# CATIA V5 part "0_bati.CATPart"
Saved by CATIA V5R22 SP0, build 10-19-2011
Part number: 0_bati
Bounding box of the stored display mesh (mm): x -17 to 20, y -50 to 50, z -50 to 50
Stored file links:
  C:\Users\pelt\Documents\0_TOTAL_ENIB_2022\0_COURS\EDM\S2\0_S2_EDM_2024P\10_rattrapage S2 EDM\0_bati.CATPart
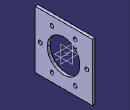
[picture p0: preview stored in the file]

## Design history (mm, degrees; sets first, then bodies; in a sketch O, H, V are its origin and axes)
Body1 (main body)
  Sketch1 on yz-plane, origin (0, 0, 0), H (0, 1, 0), V (0, 0, 1)
    line L1 (-50, 50) -> (50, 50)
    line L2 (50, 50) -> (50, -50)
    line L3 (50, -50) -> (-50, -50)
    line L4 (-50, -50) -> (-50, 50)
    reference intersected line E1 through (0, 0) direction (0, 1) from zx-plane
    reference intersected line E2 through (0, 0) direction (-1, 0) from xy-plane
    circle A1 centre (0, 0) radius 28.5
    point P5 (0, 0)
    reference intersected line E3 through (0, 0) direction (0, 1) from zx-plane
    reference intersected line E4 through (0, 0) direction (-1, 0) from xy-plane
    distance L2 L4 = 100
    distance L1 L3 = 100
    radius A1 = 28.5
    horizontal: L1 H, L3 H
    vertical: L2 V, L4 V
    symmetry: L2 L4 E1, L1 L3 E2
    coincidence: P5 E3, P5 E4
  Pad1: profile Sketch1, direction (1, 0, 0), length 5
  Point1: (0, 0, 0)
  Line1: type Normal, RefPoint Point1, RefSkin yz-plane, Start -17, End 20
  Sketch2 on end face of Pad1, origin (5, 18.6893, 39.5196), H (0, 1, 0), V (0, 0, 1)
    point P1 (21.8107, -39.5196)
    reference intersected line E1 through (0, -39.5196) direction (-1, 0) from xy-plane
    construction circle A1 centre (-18.6893, -39.5196) radius 40.5
    point P2 (-18.6893, -39.5196)
    reference intersected line E2 through (0, -39.5196) direction (-1, 0) from xy-plane
    reference intersected line E3 through (-18.6893, 0) direction (0, 1) from zx-plane
    radius A1 = 40.5
    coincidence: P1 E1, P2 E2, P2 E3, P1 A1
  Hole1: placed by Sketch2, at (5, 40.5, 0) direction (-1, 0, 0), diameter 6.5, through (limit type 6)
  CircPattern1: of Hole1, instances 6, angular step 60 {= 360.0*1 deg/CircPattern1.AngularNumber}, axis from Line1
